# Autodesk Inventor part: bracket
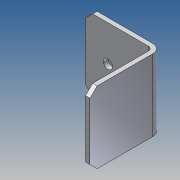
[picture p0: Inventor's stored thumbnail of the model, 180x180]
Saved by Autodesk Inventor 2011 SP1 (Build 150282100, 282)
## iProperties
Created: 2007-08
Part Number: bracket
Document SubType Name: Modeling
Designer: DaveR
Density: 1 g/cm^3
Mass: 15.4677 g
Surface Area: 107.284 cm^2
Volume: 15.4677 cm^3
Author: DaveR
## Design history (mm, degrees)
sketch "Sketch1"
  geometry: L1 (-3.311, 44.86)-(-3.311, -5.94); L2 (-3.311, -5.94)-(47.489, -5.94); L3 (47.489, -5.94)-(47.489, -2.765); L4 (47.489, -2.765)-(-0.136, -2.765); L5 (-0.136, -2.765)-(-0.136, 44.86); L6 (-0.136, 44.86)-(-3.311, 44.86)
  constraints: 12 end point, 2 parallel, 2 perpendicular, 1 vertical
  dimensions: "base_thickness" = 3.175 distance of L2.end L3.end; "flange_thickness" = 3.175 distance of L5.end L1.start; "base_length" = 50.8 distance of L1.end L2.end; "flange_height" = 50.8 distance of L1.start L1.end
extrude "main_body" new body sketch "Sketch1" taper "draft_dont_use" = 0 deg; stored distance "bracket_width" = 50.8
chamfer "Chamfers" distance "chamfer" = 5.08; stored, may be unused: second distance "d25" = 3.175, angle "d26" = 45 deg
hole "base_hole" stored, may be unused: countersink angle "d12" = 82 deg, drill point angle "d14" = 118 deg; dims "d9" = 12.7, "d10" = 9.525, "d11" = 6.35, "d13" = 19.05
pattern_linear "base_hole_pattern" dims "spacing_between_base_holes" = 19.05 (derived)
hole "flange_hole" stored, may be unused: countersink angle "d21" = 82 deg, drill point angle "d23" = 118 deg; dims "d18" = 12.7, "d19" = 9.525, "d20" = 6.35, "d22" = 19.05
pattern_linear "flange_hole_pattern" dims "spacing_between_flange_holes" = 19.05 (derived)
fillet "Inside_fillet" dims "inside_rad" = 3.175
fillet "Outside_fillet" dims "outside_rad" = 6.35 (= inside_rad + flange_thickness)
sketch "Sketch2"
  geometry: L1 (-0.136, 9.935)-(12.564, -2.765); L2 (-0.136, 39.78)-(-0.136, 0.41) reference; L3 (3.039, -2.765)-(42.409, -2.765) reference; 2 further points
  constraints: 2 end point, 2 point on line
  dimensions: "rib_angle" = 45 deg angle of L3 L1; "rib_height" = 12.7 distance from line of L3 L1.start
feature "center_rib" sketch "Sketch2" dims "d31" = 2.54, "rib_thickness" = 2.38125 (= 0.75 x flange_thickness), "rib_draft_dont_use" = 0
pattern_linear "rib_pattern" dims "spacing_between_ribs" = 10.31875
body "Solid1"
